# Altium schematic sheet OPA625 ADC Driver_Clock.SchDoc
size 431 x 279 mm; Date: Not shown in title block; ApprovedBy: Not shown in title block; CheckedBy: Not shown in title block; Author: Not shown in title block; CompanyName: Not shown in title block; Engineer: Not shown in title block; Organization: Not shown in title block; Address1: Not shown in title block; Address2: Not shown in title block; Address3: Not shown in title block; Address4: Not shown in title block; DocumentNumber: 7; Revision: Use project parameter SCH_Rev; SheetNumber: 7; SheetTotal: 8; PageSetup: Record=PageOptions¦CenterHorizontal=True¦CenterVertical=True¦PrintScale=0.96¦XCorrection=1.00¦YCorrection=1.00¦PrintKind=0¦BorderSize=5000000¦LeftOffset=0¦BottomOffset=0¦Orientation=2¦PaperLength=1000¦PaperWidth=1000¦Scale=100¦PaperSource=15¦PrintQuality=-3¦MediaType=1¦DitherType=10¦PrintScaleMode=1¦PaperKind=Tabloid (11 x 17")¦PaperIndex=17
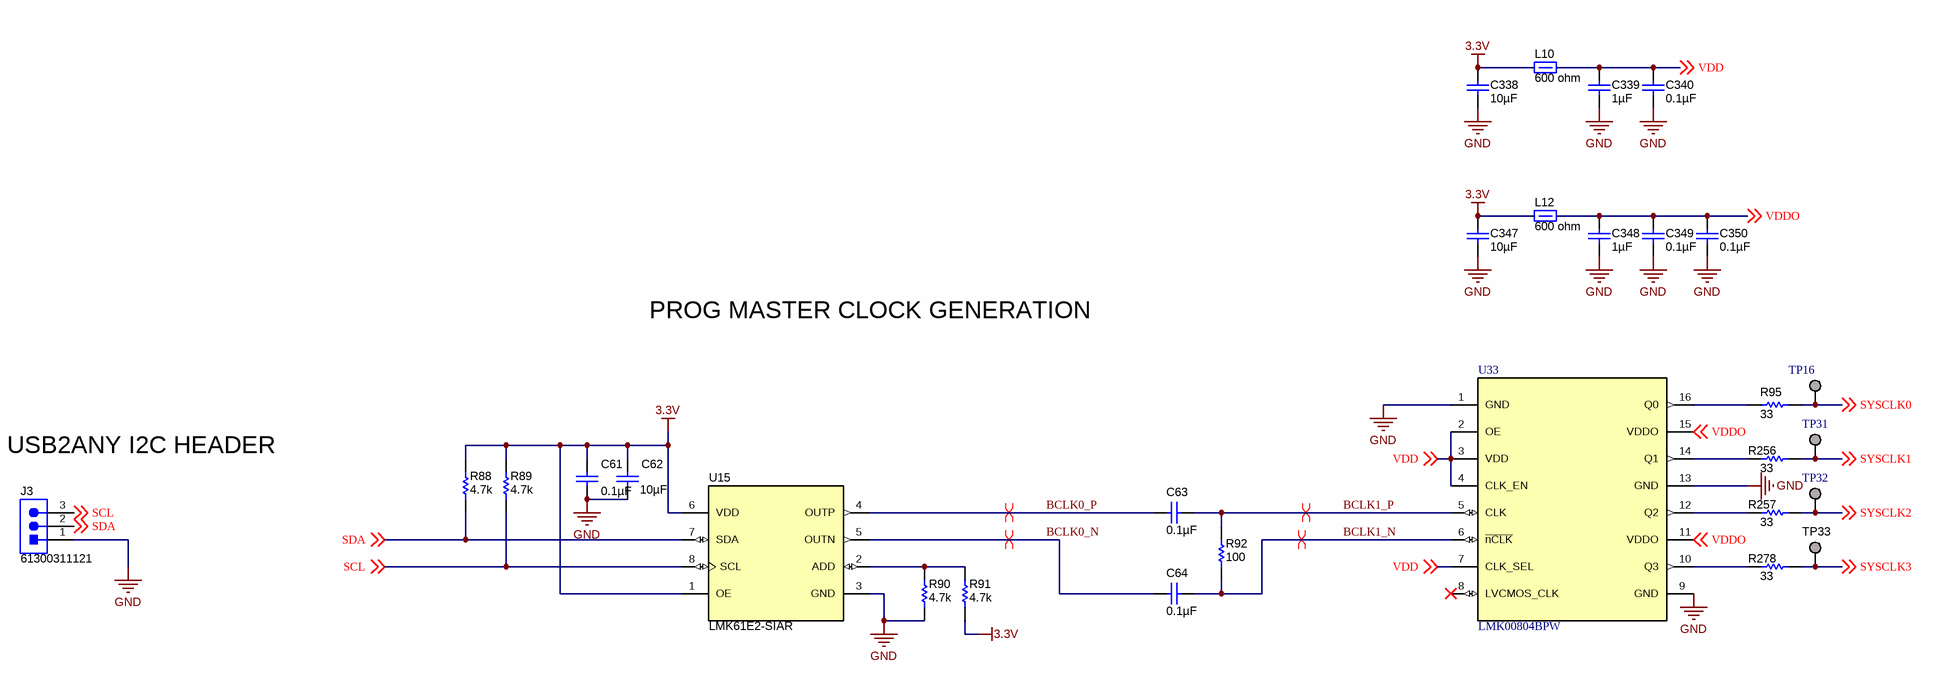
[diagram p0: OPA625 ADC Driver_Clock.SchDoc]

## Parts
C61  ValueDisplayed: 0.1µF  [0603]  (hidden comment: C0603C104J3RACTU)
C62  ValueDisplayed: 10µF  [0603_120]  (hidden comment: ZRB18AD71A106KE01L)
C63  ValueDisplayed: 0.1µF  [0402]  (hidden comment: GRM155R61E104KA87D)
C64  ValueDisplayed: 0.1µF  [0402]  (hidden comment: GRM155R61E104KA87D)
C338  ValueDisplayed: 10µF  [0805_HV]  (hidden comment: GRM21BR71A106KE51L)
C339  ValueDisplayed: 1µF  [0603]  (hidden comment: GRM188R71E105KA12D)
C340  ValueDisplayed: 0.1µF  [0402]  (hidden comment: GRM155R71C104KA88D)
C347  ValueDisplayed: 10µF  [0805_HV]  (hidden comment: GRM21BR71A106KE51L)
C348  ValueDisplayed: 1µF  [0603]  (hidden comment: GRM188R71E105KA12D)
C349  ValueDisplayed: 0.1µF  [0402]  (hidden comment: GRM155R71C104KA88D)
C350  ValueDisplayed: 0.1µF  [0402]  (hidden comment: GRM155R71C104KA88D)
J3  61300311121  [WURTH_61300311121]
L10  value 600 ohm  [0805_HV]  (hidden comment: MPZ2012S601A)
L12  value 600 ohm  [0805_HV]  (hidden comment: MPZ2012S601A)
R88  ValueDisplayed: 4.7k  [0402]  (hidden comment: CRCW04024K70JNED)
R89  ValueDisplayed: 4.7k  [0402]  (hidden comment: CRCW04024K70JNED)
R90  ValueDisplayed: 4.7k  [0402]  (hidden comment: CRCW04024K70JNED)
R91  ValueDisplayed: 4.7k  [0402]  (hidden comment: CRCW04024K70JNED)
R92  ValueDisplayed: 100  [0402]  (hidden comment: CRCW0402100RJNED)
R95  ValueDisplayed: 33  [0402]  (hidden comment: CRCW040233R0JNED)
R256  ValueDisplayed: 33  [0402]  (hidden comment: CRCW040233R0JNED)
R257  ValueDisplayed: 33  [0402]  (hidden comment: CRCW040233R0JNED)
R278  ValueDisplayed: 33  [0402]  (hidden comment: CRCW040233R0JNED)
TP16  Pogo Pad  [PogoPad]  (value not drawn)  (no BOM)
TP31  Pogo Pad  [PogoPad]  (value not drawn)  (no BOM)
TP32  Pogo Pad  [PogoPad]  (value not drawn)  (no BOM)
TP33  Pogo Pad  [PogoPad]  (value not drawn)  (no BOM)
U15  LMK61E2-SIAR  [SIA0008B]
U33  LMK00804BPW  [PW0016A_N]

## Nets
3.3V: C61.1 C62.1 C338.1 C347.1 L10.2 L12.2 R88.2 R89.2 R91.1 U15.1(OE) U15.6(VDD)
GND: C61.2 C62.2 C338.2 C339.2 C340.2 C347.2 C348.2 C349.2 C350.2 J3.1 R90.1 U15.3(GND) U33.1(GND) U33.9(GND) U33.13(GND)
BCLK0_N: C64.1 U15.5(OUTN)
BCLK0_P: C63.1 U15.4(OUTP)
BCLK1_N: C64.2 R92.1 U33.6(~{nCLK})
BCLK1_P: C63.2 R92.2 U33.5(CLK)
SCL: J3.3 R89.1 U15.8(SCL) ; off-sheet SCL
SDA: J3.2 R88.1 U15.7(SDA) ; off-sheet SDA
SYSCLK0: R95.2 TP16.1 ; off-sheet SYSCLK0
SYSCLK1: R256.2 TP31.1 ; off-sheet SYSCLK1
SYSCLK2: R257.2 TP32.1 ; off-sheet SYSCLK2
SYSCLK3: R278.2 TP33.1 ; off-sheet SYSCLK3
VDD: C339.1 C340.1 L10.1 U33.2(OE) U33.3(VDD) U33.4(CLK_EN) U33.7(CLK_SEL) ; off-sheet VDD
VDDO: C348.1 C349.1 C350.1 L12.1 U33.11(VDDO) U33.15(VDDO) ; off-sheet VDDO
NetR90_2: R90.2 R91.2 U15.2(ADD)
NetR95_1: R95.1 U33.16(Q0)
NetR256_1: R256.1 U33.14(Q1)
NetR257_1: R257.1 U33.12(Q2)
NetR278_1: R278.1 U33.10(Q3)

Not connected (* = marked no-connect by the designer): U33 8(LVCMOS_CLK)*

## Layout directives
differential pair: BCLK0_N, BCLK0_P, BCLK1_N, BCLK1_P

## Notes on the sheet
- PROG MASTER CLOCK GENERATION
- USB2ANY I2C HEADER

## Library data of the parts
C61 = C0603C104J3RACTU: CAP, CERM, 0.1 µF, 25 V, +/- 5%, X7R, 0603; Manufacturer: Kemet; Polarized: N; CompType: Capacitor; Value: 0.1uF; U/M: EA; Cap_F: 0.0000001; Tolerance_%: 5; Value1: Unknown; VDC_V: 25; Value2: 25V; TaMin_C: -55; TaMax_C: 125
C62 = ZRB18AD71A106KE01L: CAP, CERM, 10 µF, 10 V, +/- 10%, X7T, 0603; Manufacturer: MuRata; Polarized: N; CompType: Capacitor; Value: 10uF; U/M: EA; Cap_F: 0.00001; Tolerance_%: 10; Value1: Unknown; Value2: 10V; TaMin_C: -55; TaMax_C: 125; Cap_Case: 0603; AEC Category: Q200
C63 C64 = GRM155R61E104KA87D: CAP, CERM, 0.1 µF, 25 V, +/- 10%, X5R, 0402; Manufacturer: MuRata; Polarized: N; CompType: Capacitor; Value: 0.1uF; U/M: EA; Cap_F: 0.0000001; Tolerance_%: 10; Value1: Unknown; VDC_V: 25; Value2: 25V; TaMin_C: -55; TaMax_C: 85; AEC Category: Q200
C338 C347 = GRM21BR71A106KE51L: CAP, CERM, 10 µF, 10 V, +/- 10%, X7R, 0805; Manufacturer: MuRata; Polarized: N; CompType: Capacitor; Value: 10uF; U/M: EA; Cap_F: 0.00001; Tolerance_%: 10; ESR_ohm: 0.003; Value1: 0.003 ohm; Value2: 10V; TaMin_C: -55; TaMax_C: 125; Cap_Case: 0805; AEC Category: Q200
C339 C348 = GRM188R71E105KA12D: CAP, CERM, 1 µF, 25 V, +/- 10%, X7R, 0603; Manufacturer: MuRata; Polarized: N; CompType: Capacitor; Value: 1uF; U/M: EA; Cap_F: 0.000001; Tolerance_%: 10; Value1: Unknown; VDC_V: 25; Value2: 25V; TaMin_C: -55; TaMax_C: 125; AEC Category: Q200
C340 C349 C350 = GRM155R71C104KA88D: CAP, CERM, 0.1 µF, 16 V, +/- 10%, X7R, 0402; Manufacturer: MuRata; Polarized: N; CompType: Capacitor; Value: 0.1uF; U/M: EA; Cap_F: 0.0000001; Tolerance_%: 10; Value1: Unknown; VDC_V: 16; Value2: 16V; TaMin_C: -55; TaMax_C: 125
J3 = 61300311121: Header, 2.54 mm, 3x1, Gold, TH; Manufacturer: Wurth Elektronik eiSos; SymbolCreator: a0799628; U/M: EA
L10 L12 = MPZ2012S601A: Ferrite Bead, 600 ohm @ 100MHz, 2A, 0805; Manufacturer: TDK; Imax_A: 2; DCR_ohm: 0.1; Value1: 0.1 ohm; ZTyp@100MHz_Ohm: 600
R88-R91 = CRCW04024K70JNED: RES, 4.7 k, 5%, 0.063 W, 0402; Manufacturer: Vishay-Dale; CompType: Resistor; Value: 4.7k; Res_ohm: 4700; Value_Code: 4k70; Tolerance_%: 5; Power_W: 0.063; Value2: 0.063W; VDC_V: 50; TempCo: 200 ppm/C; EIA_Code: E24; U/M: EA; AEC Category: Q200
R92 = CRCW0402100RJNED: RES, 100, 5%, 0.063 W, 0402; Manufacturer: Vishay-Dale; CompType: Resistor; Value: 100; Value_Code: 100R; Tolerance_%: 5; Power_W: 0.063; Value2: 0.063W; VDC_V: 50; TempCo: 200 ppm/C; EIA_Code: E24; U/M: EA; AEC Category: Q200
R95 R256 R257 R278 = CRCW040233R0JNED: RES, 33, 5%, 0.063 W, 0402; Manufacturer: Vishay-Dale; CompType: Resistor; Value: 33; Value_Code: 33R0; Tolerance_%: 5; Power_W: 0.063; Value2: 0.063W; VDC_V: 50; TempCo: 200 ppm/C; EIA_Code: E24; U/M: EA; AEC Category: Q200
TP16 TP31-TP33 = PogoPad: Pad for Pogo Pin Connector; SymbolCreator: codlsc
U15 = LMK61E2-SIAR: Ultra-Low Jitter Programmable Oscillator with Internal EEPROM, SIA0008B; Alternate PartNumber: LMK61E2-SIAT; Manufacturer: Texas Instruments; SymbolCreator: Altium; CompType: IC; U/M: EA
U33 = LMK00804BPW: Low Skew, 1-to-4 Multiplexed Differential/LVCMOS-to-LVCMOS/TTL Fanout Buffer, PW0016A; Manufacturer: Texas Instruments; SymbolCreator: a0411947; SizeArea_mm2: 32; SizeAreaWB_mm2: 58.8; SizeX_mm: 6.4; SizeY_mm: 5; SizeZ_mm: 1.2; CompType: IC; U/M: EA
